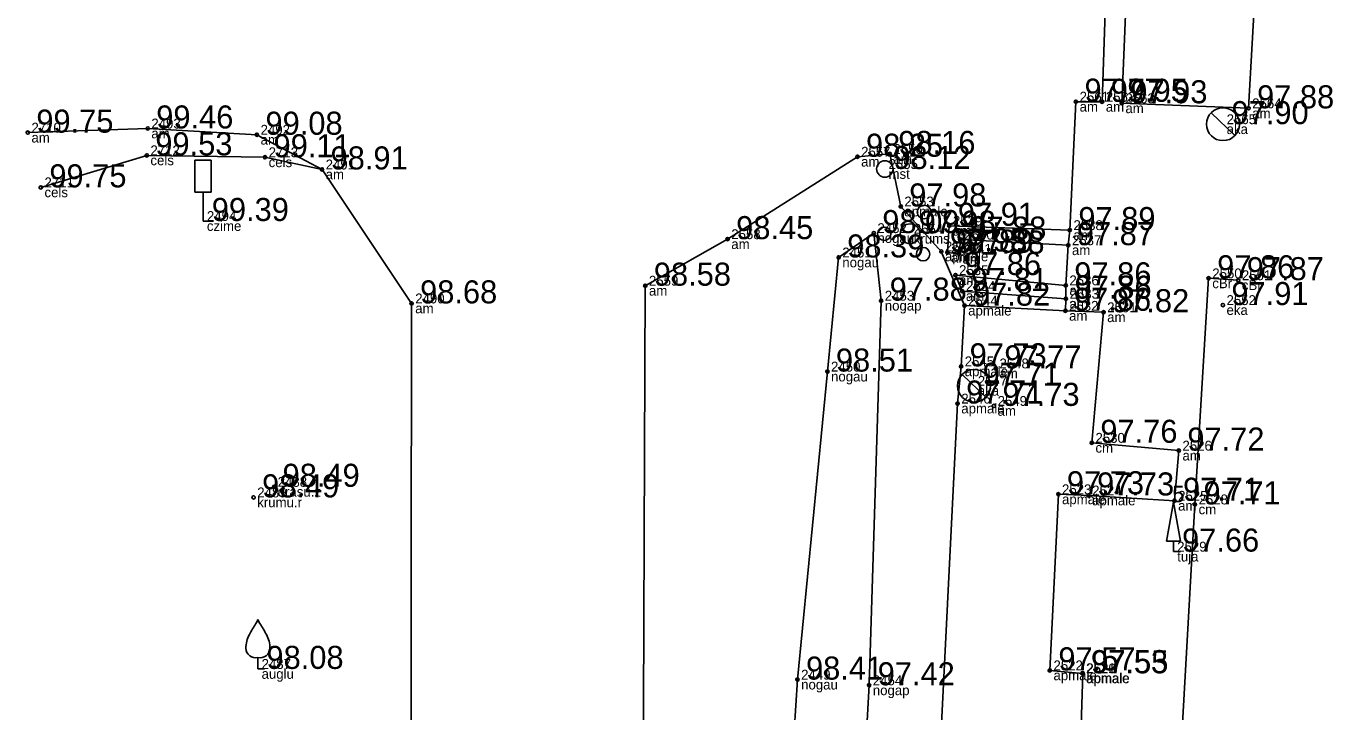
# Model space of a CAD drawing. Extents: x 614911 to 615803, y 262110 to 264311.
# Drawn here: x 615614.48 to 615654.17, y 263716.11 to 263736.94 of the extents above; entities that cross this region are included whole.
import ezdxf

# ---------------------------------------------------------------- set-up
doc = ezdxf.new("R2010")
doc.units = 0
for name, color, linetype in [('Level 1', 7, 'Continuous'), ('Level 12', 7, 'Continuous'), ('Level 14', 7, 'Continuous'), ('Level 16', 7, 'Continuous'), ('Level 31', 7, 'Continuous'), ('Level 37', 7, 'Continuous'), ('Level 53', 7, 'Continuous'), ('Level 54', 7, 'Continuous'), ('Level 57', 7, 'Continuous'), ('Level 58', 7, 'Continuous')]:
    doc.layers.add(name, color=color, linetype=linetype)

msp = doc.modelspace()

# ---------------------------------------------------------------- linework, layer by layer
at = {"layer": 'Level 1'}
for p, q in [((615649.328, 263720.981), (615649.328, 263721.301)), ((615649.328, 263720.981), (615649.538, 263720.981)), ((615621.516, 263717.771), (615621.516, 263717.419)), ((615621.516, 263717.419), (615621.716, 263717.419))]:
    msp.add_line(p, q, dxfattribs=at)
msp.add_lwpolyline([(615649.118, 263721.301), (615649.538, 263721.301), (615649.328, 263722.481)], close=True, dxfattribs=at)
for centre, radius in [((615641.753, 263731.294), 0.207), ((615640.542, 263730.634), 0.204), ((615641.326, 263730.634), 0.301), ((615641.721, 263730.014), 0.205)]:
    msp.add_circle(centre, radius, dxfattribs=at)
for centre, radius, start, end in [((615621.099, 263719.057), 0.439, 324.3837, 341.712), ((615621.933, 263719.057), 0.439, 198.288, 215.6163), ((615634.141, 263711.023), 14.88, 148.4844, 149.9901), ((615608.891, 263711.023), 14.88, 30.0099, 31.5156), ((615622.04, 263718.044), 0.89, 151.757, 179.9138), ((615620.992, 263718.044), 0.89, 0.0862, 28.243), ((615621.44, 263718.05), 0.29, 181.0782, 285.2823), ((615621.592, 263718.05), 0.29, 254.7177, 358.9218)]:
    msp.add_arc(centre, radius, start, end, dxfattribs=at)
at = {"layer": 'Level 12'}
for p, q in [((615650.471, 263734.31), (615651.189, 263733.614)), ((615642.912, 263726.364), (615643.63, 263725.668))]:
    msp.add_line(p, q, dxfattribs=at)
for centre in [(615650.83, 263733.962), (615643.271, 263726.016)]:
    msp.add_circle(centre, 0.5, dxfattribs=at)
at = {"layer": 'Level 14'}
msp.add_circle((615640.559, 263732.602), 0.25, dxfattribs=at)
at = {"layer": 'Level 16'}
for p, q in [((615620.101, 263732.868), (615619.601, 263732.868)), ((615619.601, 263731.899), (615619.601, 263732.868)), ((615620.101, 263731.899), (615620.101, 263732.868)), ((615620.101, 263731.899), (615619.601, 263731.899)), ((615619.855, 263731.899), (615619.855, 263731.021)), ((615619.855, 263731.021), (615620.17, 263731.021))]:
    msp.add_line(p, q, dxfattribs=at)
at = {"layer": 'Level 31'}
for points in [[(615640.222, 263730.654), (615639.156, 263729.914), (615638.813, 263726.449), (615637.905, 263717.094), (615637.4, 263709.206), (615636.622, 263706.978), (615634.131, 263706.112), (615634.079, 263701.899), (615635.299, 263700.645), (615638.093, 263700.376), (615638.66, 263699.329), (615639.457, 263698.928)], [(615639.457, 263698.928), (615639.243, 263700.218), (615638.615, 263701.392), (615635.987, 263701.822), (615635.625, 263703.98), (615637.738, 263705.304), (615639.592, 263708.219), (615640.082, 263716.921), (615640.446, 263728.602), (615640.222, 263730.654)]]:
    msp.add_lwpolyline(points, dxfattribs=at)
at = {"layer": 'Level 37'}
msp.add_line((615646.044, 263728.294), (615642.979, 263728.451), dxfattribs=at)
for points in [[(615651.606, 263734.443), (615651.832, 263738.39), (615649.871, 263738.484), (615650.088, 263738.952), (615650.857, 263753.018), (615651.332, 263761.95), (615649.157, 263762.02), (615649.56, 263765.661)], [(615646.42, 263712.583), (615646.571, 263717.284), (615645.57, 263717.375), (615645.829, 263722.722), (615646.745, 263722.686), (615649.356, 263722.525), (615649.488, 263724.049), (615646.845, 263724.286), (615647.201, 263728.251), (615646.044, 263728.294), (615646.06, 263728.662), (615646.054, 263729.067), (615646.131, 263730.287), (615646.177, 263730.745), (615646.364, 263734.645), (615647.16, 263734.641), (615647.309, 263739.2)], [(615651.606, 263734.443), (615647.755, 263734.597), (615647.941, 263739.002), (615649.871, 263738.484)], [(615614.526, 263733.705), (615618.168, 263733.831), (615621.486, 263733.641), (615623.463, 263732.587)], [(615614.922, 263732.043), (615618.14, 263733.015), (615621.731, 263732.957), (615623.463, 263732.587)], [(615623.463, 263732.587), (615626.183, 263728.519), (615626.162, 263711.199), (615626.355, 263695.987), (615626.569, 263669.393), (615626.624, 263652.989), (615626.609, 263646.28), (615624.319, 263644.804), (615621.47, 263643.747), (615617.37, 263642.483)], [(615646.177, 263730.745), (615642.517, 263730.876), (615642.46, 263730.06), (615642.807, 263730.028), (615642.863, 263730.456), (615646.131, 263730.287)], [(615646.054, 263729.067), (615642.702, 263729.379), (615642.91, 263728.895), (615646.06, 263728.662)], [(615651.292, 263729.224), (615650.394, 263729.281), (615649.978, 263722.415), (615649.195, 263708.559), (615647.127, 263708.833)]]:
    msp.add_lwpolyline(points, dxfattribs=at)
msp.add_lwpolyline([(615641.246, 263697.532), (615638.026, 263697.736), (615634.864, 263699.629), (615633.172, 263700.964), (615633.282, 263729.057), (615635.783, 263730.47), (615639.727, 263732.973), (615640.708, 263733.057), (615641.041, 263731.463), (615642.275, 263730.097), (615642.979, 263728.451), (615642.874, 263726.607), (615642.77, 263725.478), (615642.162, 263713.315), (615641.444, 263698.541)], close=True, dxfattribs=at)
at = {"layer": 'Level 57'}
for centre in [(615646.364, 263734.645), (615647.16, 263734.641), (615647.755, 263734.597), (615651.606, 263734.443), (615614.526, 263733.705), (615618.168, 263733.831), (615621.486, 263733.641), (615618.14, 263733.015), (615621.731, 263732.957), (615639.727, 263732.973), (615640.708, 263733.057), (615623.463, 263732.587), (615614.922, 263732.043), (615641.041, 263731.463), (615642.517, 263730.876), (615646.177, 263730.745), (615635.783, 263730.47), (615640.222, 263730.654), (615642.863, 263730.456), (615642.275, 263730.097), (615642.46, 263730.06), (615642.807, 263730.028), (615646.131, 263730.287), (615639.156, 263729.914), (615642.702, 263729.379), (615650.394, 263729.281), (615651.292, 263729.224), (615633.282, 263729.057), (615642.91, 263728.895), (615646.054, 263729.067), (615626.183, 263728.519), (615640.446, 263728.602), (615642.979, 263728.451), (615646.06, 263728.662), (615650.826, 263728.468), (615646.044, 263728.294), (615647.201, 263728.251), (615638.813, 263726.449), (615642.874, 263726.607), (615643.929, 263726.545), (615642.77, 263725.478), (615643.872, 263725.407), (615646.845, 263724.286), (615649.488, 263724.049), (615622.006, 263722.949), (615621.384, 263722.628), (615645.829, 263722.722), (615646.745, 263722.686), (615649.356, 263722.525), (615649.978, 263722.415), (615645.57, 263717.375), (615646.559, 263717.29), (615646.571, 263717.284), (615637.905, 263717.094), (615640.082, 263716.921)]:
    msp.add_circle(centre, 0.05, dxfattribs=at)
at = {"layer": 'Level 58'}
for centre in [(615646.364, 263734.645), (615647.16, 263734.641), (615647.755, 263734.597), (615651.606, 263734.443), (615614.526, 263733.705), (615618.168, 263733.831), (615621.486, 263733.641), (615618.14, 263733.015), (615621.731, 263732.957), (615639.727, 263732.973), (615640.708, 263733.057), (615623.463, 263732.587), (615614.922, 263732.043), (615641.041, 263731.463), (615642.517, 263730.876), (615646.177, 263730.745), (615635.783, 263730.47), (615640.222, 263730.654), (615642.863, 263730.456), (615642.275, 263730.097), (615642.46, 263730.06), (615642.807, 263730.028), (615646.131, 263730.287), (615639.156, 263729.914), (615642.702, 263729.379), (615650.394, 263729.281), (615651.292, 263729.224), (615633.282, 263729.057), (615642.91, 263728.895), (615646.054, 263729.067), (615626.183, 263728.519), (615640.446, 263728.602), (615642.979, 263728.451), (615646.06, 263728.662), (615650.826, 263728.468), (615646.044, 263728.294), (615647.201, 263728.251), (615638.813, 263726.449), (615642.874, 263726.607), (615643.929, 263726.545), (615642.77, 263725.478), (615643.872, 263725.407), (615646.845, 263724.286), (615649.488, 263724.049), (615622.006, 263722.949), (615621.384, 263722.628), (615645.829, 263722.722), (615646.745, 263722.686), (615649.356, 263722.525), (615649.978, 263722.415), (615645.57, 263717.375), (615646.559, 263717.29), (615646.571, 263717.284), (615637.905, 263717.094), (615640.082, 263716.921)]:
    msp.add_circle(centre, 0.05, dxfattribs=at)

# ---------------------------------------------------------------- texts
at = {"layer": 'Level 1'}
msp.add_text(' 5', height=0.5, dxfattribs=at).set_placement((615649.103, 263722.481))
at = {"layer": 'Level 53'}
for s, p in [(' am', (615646.364, 263734.345)), (' am', (615647.16, 263734.341)), (' am', (615647.755, 263734.297)), (' am', (615651.606, 263734.143)), (' aka', (615650.83, 263733.662)), (' am', (615614.526, 263733.405)), (' am', (615618.168, 263733.531)), (' am', (615621.486, 263733.341)), (' cels', (615618.14, 263732.715)), (' cels', (615621.731, 263732.657)), (' am', (615639.727, 263732.673)), (' am', (615640.708, 263732.757)), (' am', (615623.463, 263732.287)), (' mst', (615640.559, 263732.302)), (' cels', (615614.922, 263731.743)), (' apmale', (615641.041, 263731.163)), (' czime', (615619.855, 263730.721)), (' am', (615642.517, 263730.576)), (' am', (615635.783, 263730.17)), (' nogau', (615640.222, 263730.354)), (' krums', (615641.326, 263730.334)), (' am', (615642.863, 263730.156)), (' am', (615646.177, 263730.445)), (' apmale', (615642.275, 263729.797)), (' am', (615642.46, 263729.76)), (' am', (615646.131, 263729.987)), (' nogau', (615639.156, 263729.614)), (' am', (615642.807, 263729.728)), (' am', (615642.702, 263729.079)), (' cBr', (615650.394, 263728.981)), (' cBr', (615651.292, 263728.924)), (' am', (615633.282, 263728.757)), (' am', (615642.91, 263728.595)), (' am', (615646.054, 263728.767)), (' am', (615626.183, 263728.219)), (' nogap', (615640.446, 263728.302)), (' apmale', (615642.979, 263728.151)), (' am', (615646.06, 263728.362)), (' eka', (615650.826, 263728.168)), (' am', (615646.044, 263727.994)), (' am', (615647.201, 263727.951)), (' apmale', (615642.874, 263726.307)), (' am', (615643.929, 263726.245)), (' nogau', (615638.813, 263726.149)), (' aka', (615643.271, 263725.716)), (' apmale', (615642.77, 263725.178)), (' am', (615643.872, 263725.107)), (' cm', (615646.845, 263723.986)), (' am', (615649.488, 263723.749)), (' drasu.z', (615622.006, 263722.649)), (' krumu.r', (615621.384, 263722.328)), (' apmale', (615645.829, 263722.422)), (' apmale', (615646.745, 263722.386)), (' am', (615649.356, 263722.225)), (' cm', (615649.978, 263722.115)), (' tuja', (615649.328, 263720.681)), (' auglu', (615621.516, 263717.119)), (' apmale', (615645.57, 263717.075)), (' apmale', (615646.559, 263716.99)), (' apmale', (615646.571, 263716.984)), (' nogau', (615637.905, 263716.794)), (' nogap', (615640.082, 263716.621))]:
    msp.add_text(s, height=0.3, dxfattribs=at).set_placement(p)
at = {"layer": 'Level 54'}
for s, p in [(' 2561', (615646.364, 263734.645)), (' 2562', (615647.16, 263734.641)), (' 2563', (615647.755, 263734.597)), (' 2564', (615651.606, 263734.443)), (' 2710', (615614.526, 263733.705)), (' 2493', (615618.168, 263733.831)), (' 2565', (615650.83, 263733.962)), (' 2492', (615621.486, 263733.641)), (' 2712', (615618.14, 263733.015)), (' 2713', (615621.731, 263732.957)), (' 2557', (615639.727, 263732.973)), (' 2556', (615640.708, 263733.057)), (' 2491', (615623.463, 263732.587)), (' 2555', (615640.559, 263732.602)), (' 2711', (615614.922, 263732.043)), (' 2553', (615641.041, 263731.463)), (' 2494', (615619.855, 263731.021)), (' 2452', (615640.222, 263730.654)), (' 2554', (615641.326, 263730.634)), (' 2539', (615642.517, 263730.876)), (' 2538', (615646.177, 263730.745)), (' 2558', (615635.783, 263730.47)), (' 2543', (615642.275, 263730.097)), (' 2540', (615642.863, 263730.456)), (' 2537', (615646.131, 263730.287)), (' 2451', (615639.156, 263729.914)), (' 2542', (615642.46, 263730.06)), (' 2541', (615642.807, 263730.028)), (' 2535', (615642.702, 263729.379)), (' 2559', (615633.282, 263729.057)), (' 2534', (615642.91, 263728.895)), (' 2536', (615646.054, 263729.067)), (' 2550', (615650.394, 263729.281)), (' 2551', (615651.292, 263729.224)), (' 2490', (615626.183, 263728.519)), (' 2453', (615640.446, 263728.602)), (' 2533', (615646.06, 263728.662)), (' 2544', (615642.979, 263728.451)), (' 2532', (615646.044, 263728.294)), (' 2531', (615647.201, 263728.251)), (' 2552', (615650.826, 263728.468)), (' 2545', (615642.874, 263726.607)), (' 2548', (615643.929, 263726.545)), (' 2450', (615638.813, 263726.449)), (' 2547', (615643.271, 263726.016)), (' 2546', (615642.77, 263725.478)), (' 2549', (615643.872, 263725.407)), (' 2530', (615646.845, 263724.286)), (' 2526', (615649.488, 263724.049)), (' 2488', (615622.006, 263722.949)), (' 2489', (615621.384, 263722.628)), (' 2523', (615645.829, 263722.722)), (' 2524', (615646.745, 263722.686)), (' 2525', (615649.356, 263722.525)), (' 2528', (615649.978, 263722.415)), (' 2529', (615649.328, 263720.981)), (' 2487', (615621.516, 263717.419)), (' 2449', (615637.905, 263717.094)), (' 2522', (615645.57, 263717.375)), (' 2521', (615646.559, 263717.29)), (' 2520', (615646.571, 263717.284)), (' 2454', (615640.082, 263716.921))]:
    msp.add_text(s, height=0.3, dxfattribs=at).set_placement(p)
at = {"layer": 'Level 58'}
for s, p in [(' 97.97', (615646.364, 263734.645)), (' 97.95', (615647.16, 263734.641)), (' 97.93', (615647.755, 263734.597)), (' 97.88', (615651.606, 263734.443)), (' 99.75', (615614.526, 263733.705)), (' 99.46', (615618.168, 263733.831)), (' 97.90', (615650.83, 263733.962)), (' 99.08', (615621.486, 263733.641)), (' 99.53', (615618.14, 263733.015)), (' 99.11', (615621.731, 263732.957)), (' 98.25', (615639.727, 263732.973)), (' 98.16', (615640.708, 263733.057)), (' 98.91', (615623.463, 263732.587)), (' 98.12', (615640.559, 263732.602)), (' 99.75', (615614.922, 263732.043)), (' 97.98', (615641.041, 263731.463)), (' 99.39', (615619.855, 263731.021)), (' 97.91', (615642.517, 263730.876)), (' 98.09', (615640.222, 263730.654)), (' 97.98', (615641.326, 263730.634)), (' 97.89', (615646.177, 263730.745)), (' 98.45', (615635.783, 263730.47)), (' 97.95', (615642.275, 263730.097)), (' 97.88', (615642.863, 263730.456)), (' 97.87', (615646.131, 263730.287)), (' 98.39', (615639.156, 263729.914)), (' 97.89', (615642.46, 263730.06)), (' 97.88', (615642.807, 263730.028)), (' 97.86', (615642.702, 263729.379)), (' 97.86', (615650.394, 263729.281)), (' 98.58', (615633.282, 263729.057)), (' 97.81', (615642.91, 263728.895)), (' 97.86', (615646.054, 263729.067)), (' 97.87', (615651.292, 263729.224)), (' 98.68', (615626.183, 263728.519)), (' 97.88', (615640.446, 263728.602)), (' 97.86', (615646.06, 263728.662)), (' 97.82', (615642.979, 263728.451)), (' 97.86', (615646.044, 263728.294)), (' 97.82', (615647.201, 263728.251)), (' 97.91', (615650.826, 263728.468)), (' 97.73', (615642.874, 263726.607)), (' 97.77', (615643.929, 263726.545)), (' 98.51', (615638.813, 263726.449)), (' 97.71', (615643.271, 263726.016)), (' 97.71', (615642.77, 263725.478)), (' 97.73', (615643.872, 263725.407)), (' 97.76', (615646.845, 263724.286)), (' 97.72', (615649.488, 263724.049)), (' 98.49', (615622.006, 263722.949)), (' 98.49', (615621.384, 263722.628)), (' 97.73', (615645.829, 263722.722)), (' 97.73', (615646.745, 263722.686)), (' 97.71', (615649.356, 263722.525)), (' 97.71', (615649.978, 263722.415)), (' 97.66', (615649.328, 263720.981)), (' 98.08', (615621.516, 263717.419)), (' 97.57', (615645.57, 263717.375)), (' 98.41', (615637.905, 263717.094)), (' 97.53', (615646.559, 263717.29)), (' 97.55', (615646.571, 263717.284)), (' 97.42', (615640.082, 263716.921))]:
    msp.add_text(s, height=0.7, dxfattribs=at).set_placement(p)

doc.saveas('drawing.dxf')
